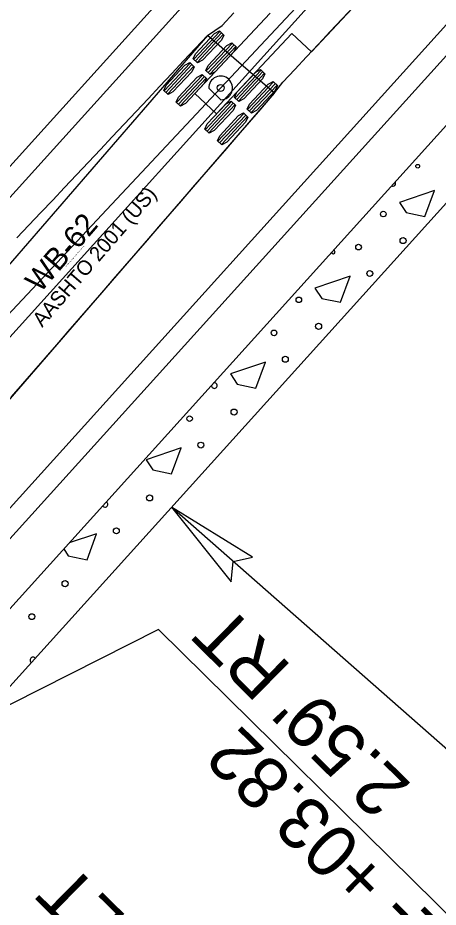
# Model space of a CAD drawing. Extents: x 1262642 to 1268358, y 767825 to 773481.
# Drawn here: x 1266914.3 to 1266954.7, y 772243.3 to 772328.8 of the extents above; entities that cross this region are included whole.
import ezdxf

# ---------------------------------------------------------------- set-up
doc = ezdxf.new("R2010")
doc.units = 0
for name, color, linetype in [('Prop Conc 2ft 6in Curb and Gutter', 7, 'Continuous'), ('Prop Conc 4in Sidewalk', 7, 'Continuous'), ('Prop Dimension Text', 7, 'Continuous'), ('Prop EOT', 7, 'Continuous'), ('Prop Horizontal Alignment', 7, 'Continuous'), ('Prop Lane Lines', 7, 'Continuous'), ('Prop Terminator CELL', 7, 'Continuous'), ('Scratch_Level_3', 7, 'Continuous')]:
    doc.layers.add(name, color=color, linetype=linetype)

msp = doc.modelspace()

# ---------------------------------------------------------------- linework, layer by layer
at = {"layer": 'Prop Conc 2ft 6in Curb and Gutter'}
for p, q in [((1267174.15, 772567.197), (1266880.184, 772241.815)), ((1266883.523, 772238.798), (1267177.489, 772564.181)), ((1267181.289, 772560.929), (1266887.233, 772235.447)), ((1266954.353, 772312.18), (1266950.985, 772311.041)), ((1266953.435, 772309.68), (1266954.353, 772312.18)), ((1266950.985, 772311.041), (1266951.629, 772310.056)), ((1266951.629, 772310.056), (1266953.435, 772309.68)), ((1266946.23, 772303.935), (1266942.862, 772302.797)), ((1266945.312, 772301.436), (1266946.23, 772303.935)), ((1266942.862, 772302.797), (1266943.506, 772301.811)), ((1266943.506, 772301.811), (1266945.312, 772301.436)), ((1266938.107, 772295.691), (1266934.739, 772294.552)), ((1266937.188, 772293.192), (1266938.107, 772295.691)), ((1266934.739, 772294.552), (1266935.382, 772293.567)), ((1266935.382, 772293.567), (1266937.188, 772293.192)), ((1266929.983, 772287.447), (1266926.615, 772286.308)), ((1266929.065, 772284.947), (1266929.983, 772287.447)), ((1266926.615, 772286.308), (1266927.259, 772285.323)), ((1266927.259, 772285.323), (1266929.065, 772284.947)), ((1266921.86, 772279.202), (1266919.219, 772278.309)), ((1266920.942, 772276.703), (1266921.86, 772279.202)), ((1266918.704, 772277.739), (1266919.136, 772277.078)), ((1266919.136, 772277.078), (1266920.942, 772276.703))]:
    msp.add_line(p, q, dxfattribs=at)
for centre, radius in [((1266952.739, 772314.515), 0.18), ((1266949.428, 772309.921), 0.268), ((1266951.329, 772307.372), 0.292), ((1266947.05, 772306.743), 0.268), ((1266948.131, 772304.206), 0.285), ((1266941.305, 772301.677), 0.268), ((1266943.205, 772299.128), 0.292), ((1266938.927, 772298.498), 0.268), ((1266940.008, 772295.962), 0.285), ((1266930.804, 772290.254), 0.268), ((1266935.082, 772290.884), 0.292), ((1266931.885, 772287.717), 0.285), ((1266926.959, 772282.639), 0.292), ((1266923.762, 772279.473), 0.285), ((1266918.836, 772274.395), 0.292), ((1266915.638, 772271.228), 0.285)]:
    msp.add_circle(centre, radius, dxfattribs=at)
for centre, radius, start, end in [((1266950.349, 772312.854), 0.268, 240.53166, 35.27598), ((1266944.615, 772306.271), 0.18, 194.25187, 81.55577), ((1266933.181, 772293.432), 0.268, 171.93825, 7.0048), ((1266933.181, 772293.432), 0.268, 7.0048, 103.86939), ((1266922.68, 772282.01), 0.268, 208.77534, 67.0323), ((1266915.757, 772267.048), 0.289, 43.95867, 231.84897)]:
    msp.add_arc(centre, radius, start, end, dxfattribs=at)
at = {"layer": 'Prop Conc 4in Sidewalk'}
for p, q in [((1267177.489, 772564.181), (1266883.523, 772238.798)), ((1267181.199, 772560.829), (1266887.233, 772235.447))]:
    msp.add_line(p, q, dxfattribs=at)
at = {"layer": 'Prop Dimension Text'}
for p, q in [((1266961.771, 772252.97), (1266929.056, 772281.74)), ((1266927.819, 772269.993), (1266971.146, 772227.303))]:
    msp.add_line(p, q, dxfattribs=at)
msp.add_lwpolyline([(1266927.819, 772269.993), (1266826.047, 772218.568)], dxfattribs=at)
at = {"layer": 'Prop EOT'}
msp.add_line((1267172.665, 772568.538), (1266878.7, 772243.156), dxfattribs=at)
at = {"layer": 'Prop Horizontal Alignment'}
msp.add_line((1266770.936, 772153.71), (1267443.049, 772897.651), dxfattribs=at)
msp.add_arc((1275047.307, 780021.225), 11400, 222.9935866, 225.4043192, dxfattribs=at)
at = {"layer": 'Prop Lane Lines'}
for p, q in [((1267156.341, 772583.286), (1266860.311, 772255.619)), ((1267164.503, 772575.912), (1266868.473, 772248.245))]:
    msp.add_line(p, q, dxfattribs=at)
at = {"layer": 'Prop Terminator CELL'}
msp.add_lwpolyline([(1266936.838, 772276.96), (1266929.056, 772281.74), (1266934.796, 772274.562), (1266934.989, 772276.523)], close=True, dxfattribs=at)
at = {"layer": 'Scratch_Level_3'}
for p, q in [((1266841.285, 772223.318), (1266947.116, 772336.274)), ((1266942.516, 772325.511), (1266952.77, 772336.459)), ((1266938.55, 772329.225), (1266931.316, 772321.5)), ((1266933.711, 772327.478), (1266931.205, 772324.801)), ((1266933.879, 772327.321), (1266931.372, 772324.645)), ((1266934.046, 772327.164), (1266931.539, 772324.488)), ((1266933.408, 772319.541), (1266940.643, 772327.265)), ((1266940.643, 772327.265), (1266942.516, 772325.511)), ((1266932.537, 772327.091), (1266901.116, 772290.805)), ((1266934.916, 772326.35), (1266932.409, 772323.673)), ((1266938.963, 772321.527), (1266932.537, 772327.091)), ((1266932.537, 772327.091), (1266932.537, 772327.091)), ((1266935.083, 772326.193), (1266932.576, 772323.517)), ((1266935.25, 772326.036), (1266932.744, 772323.36)), ((1266930.863, 772324.436), (1266928.357, 772321.76)), ((1266931.03, 772324.28), (1266928.524, 772321.604)), ((1266931.198, 772324.123), (1266928.691, 772321.447)), ((1266937.677, 772323.763), (1266935.171, 772321.087)), ((1266932.067, 772323.309), (1266929.561, 772320.632)), ((1266932.235, 772323.152), (1266929.728, 772320.476)), ((1266932.402, 772322.995), (1266929.895, 772320.319)), ((1266937.844, 772323.607), (1266935.338, 772320.931)), ((1266938.012, 772323.45), (1266935.505, 772320.774)), ((1266932.644, 772322.004), (1266933.824, 772320.899)), ((1266938.881, 772322.636), (1266936.375, 772319.959)), ((1266939.049, 772322.479), (1266936.542, 772319.803)), ((1266939.216, 772322.322), (1266936.709, 772319.646)), ((1266907.541, 772285.241), (1266938.963, 772321.527)), ((1266931.316, 772321.5), (1266933.408, 772319.541)), ((1266934.829, 772320.722), (1266932.322, 772318.046)), ((1266934.996, 772320.566), (1266932.49, 772317.889)), ((1266935.163, 772320.409), (1266932.657, 772317.733)), ((1266936.033, 772319.594), (1266933.527, 772316.918)), ((1266936.2, 772319.438), (1266933.694, 772316.762)), ((1266936.368, 772319.281), (1266933.861, 772316.605))]:
    msp.add_line(p, q, dxfattribs=at)
for points in [[(1266913.694, 772292.346), (1266914.78, 772293.601), (1266915.867, 772294.855), (1266916.953, 772296.11), (1266918.041, 772297.366), (1266919.128, 772298.622), (1266920.216, 772299.878), (1266921.304, 772301.134), (1266922.393, 772302.391), (1266923.481, 772303.649), (1266924.57, 772304.906), (1266925.659, 772306.164), (1266926.749, 772307.422), (1266927.838, 772308.68), (1266928.928, 772309.938), (1266930.018, 772311.197), (1266931.108, 772312.456), (1266932.198, 772313.714), (1266933.288, 772314.974), (1266934.378, 772316.233), (1266935.469, 772317.492), (1266936.559, 772318.751), (1266937.65, 772320.011), (1266938.741, 772321.27), (1266939.772, 772322.582), (1266940.912, 772323.799), (1266942.053, 772325.016), (1266943.193, 772326.233), (1266944.333, 772327.451), (1266945.473, 772328.668), (1266946.613, 772329.885)], [(1266914.203, 772307.624), (1266915.35, 772308.838), (1266916.497, 772310.053), (1266917.643, 772311.267), (1266918.79, 772312.481), (1266919.936, 772313.696), (1266921.081, 772314.91), (1266922.227, 772316.125), (1266923.372, 772317.34), (1266924.517, 772318.554), (1266925.662, 772319.769), (1266926.807, 772320.984), (1266927.939, 772322.209), (1266929.084, 772323.424), (1266930.229, 772324.639), (1266931.373, 772325.853), (1266932.517, 772327.068), (1266933.928, 772328.052), (1266935.069, 772329.269)]]:
    msp.add_lwpolyline(points, dxfattribs=at)
for points in [[(1266933.67, 772327.516), (1266934.087, 772327.125), (1266933.862, 772326.633), (1266932.058, 772324.706), (1266931.581, 772324.449), (1266931.163, 772324.84), (1266931.388, 772325.333), (1266933.193, 772327.26)], [(1266934.874, 772326.389), (1266935.292, 772325.998), (1266935.066, 772325.505), (1266933.262, 772323.578), (1266932.785, 772323.321), (1266932.368, 772323.712), (1266932.593, 772324.205), (1266934.397, 772326.132)], [(1266930.822, 772324.475), (1266931.239, 772324.084), (1266931.014, 772323.592), (1266929.209, 772321.665), (1266928.733, 772321.408), (1266928.315, 772321.799), (1266928.54, 772322.292), (1266930.345, 772324.218)], [(1266937.635, 772323.802), (1266938.053, 772323.411), (1266937.828, 772322.919), (1266936.023, 772320.992), (1266935.547, 772320.735), (1266935.129, 772321.126), (1266935.354, 772321.619), (1266937.159, 772323.545)], [(1266932.026, 772323.347), (1266932.443, 772322.956), (1266932.218, 772322.464), (1266930.414, 772320.537), (1266929.937, 772320.28), (1266929.519, 772320.671), (1266929.745, 772321.164), (1266931.549, 772323.09)], [(1266938.84, 772322.674), (1266939.257, 772322.283), (1266939.032, 772321.791), (1266937.228, 772319.864), (1266936.751, 772319.607), (1266936.333, 772319.998), (1266936.558, 772320.491), (1266938.363, 772322.418)], [(1266934.787, 772320.761), (1266935.205, 772320.37), (1266934.98, 772319.878), (1266933.175, 772317.951), (1266932.698, 772317.694), (1266932.281, 772318.085), (1266932.506, 772318.577), (1266934.311, 772320.504)], [(1266935.992, 772319.633), (1266936.409, 772319.242), (1266936.184, 772318.75), (1266934.379, 772316.823), (1266933.903, 772316.566), (1266933.485, 772316.957), (1266933.71, 772317.45), (1266935.515, 772319.376)]]:
    msp.add_lwpolyline(points, close=True, dxfattribs=at)
msp.add_circle((1266933.786, 772322.041), 0.34, dxfattribs=at)
msp.add_arc((1266933.786, 772322.041), 1.143, 271.87638, 181.87638, dxfattribs=at)

# ---------------------------------------------------------------- texts
at = {"layer": 'Prop Dimension Text'}
for s, p in [("2.59' RT", (1266952.233, 772255.06)), ('-Y38NE- +03.82', (1266969.876, 772227.146)), ("13.73' LT", (1266939.066, 772228.336))]:
    msp.add_text(s, height=5, rotation=135.42387, dxfattribs=at).set_placement(p)
at = {"layer": 'Scratch_Level_3'}
for s, height, p in [('AASHTO 2001 (US)', 1.41667, (1266916.633, 772298.976)), ('WB-62', 2.125, (1266916.433, 772302.261)), ('(c) 2016 Transoft Solutions, Inc. All rights reserved.', 0.085, (1266918.937, 772304.829))]:
    msp.add_text(s, height=height, rotation=49.10938, dxfattribs=at).set_placement(p)

doc.saveas('drawing.dxf')
